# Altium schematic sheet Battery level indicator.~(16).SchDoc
size A3; SheetNumber: 3; SheetTotal: 7
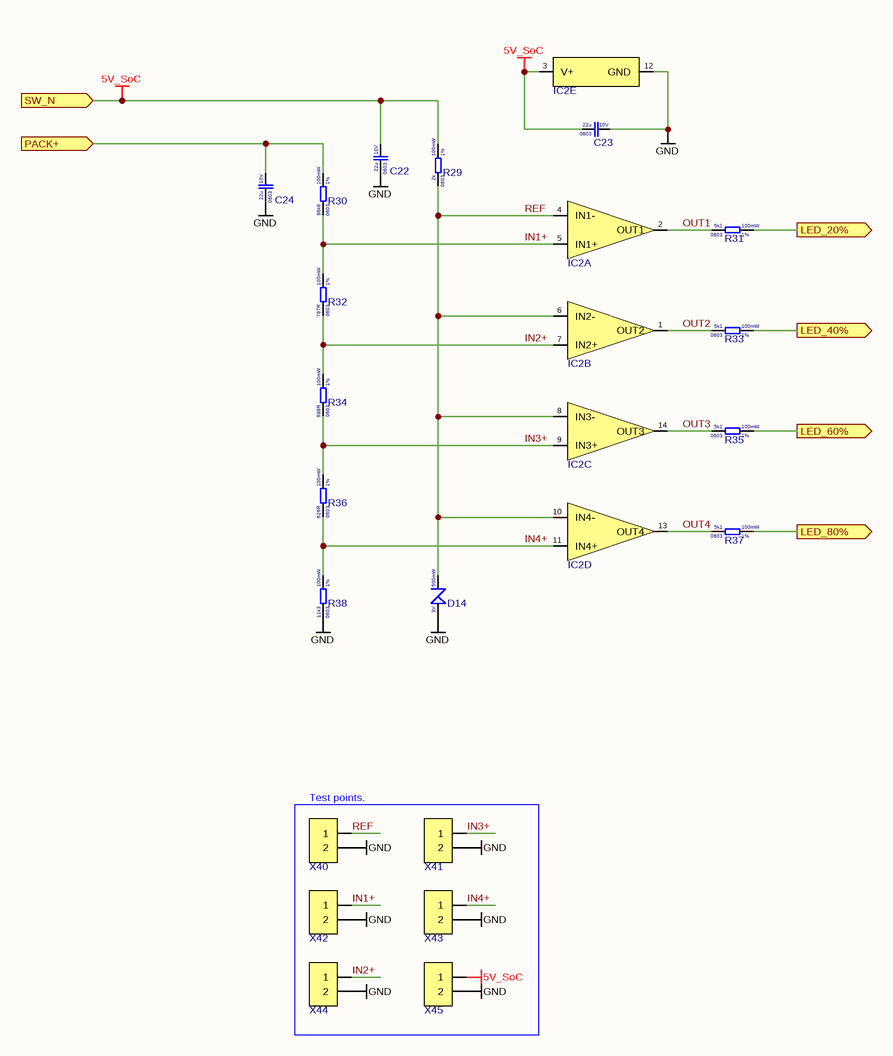
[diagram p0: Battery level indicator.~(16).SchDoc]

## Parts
C22  Voltage Rating: 10V  Case Code (Imperial): 0603  Capacitance: 22u  [CAP 0603]  (hidden comment: CGA0603X5R226M100JT)
C23  Voltage Rating: 10V  Case Code (Imperial): 0603  Capacitance: 22u  [CAP 0603]  (hidden comment: CGA0603X5R226M100JT)
C24  Voltage Rating: 10V  Case Code (Imperial): 0603  Capacitance: 22u  [CAP 0603]  (hidden comment: CGA0603X5R226M100JT)
D14  Power Rating: 500mW  Reverse Voltage: 3V  [SOD-123]  (hidden comment: BZT52C3V0)
IC2  LM339LVPWR  [TSSOP-14]  (value not drawn)  (parts A,B,C,D,E of 5)
R29  Resistance Tolerance: 1%  Resistance: 2k  Power Rating: 100mW  Case Code (Imperial): 0603  [RES_0603]  (hidden comment: 0603WAF2001T5E)
R30  Resistance Tolerance: 1%  Resistance: 86k6  Power Rating: 100mW  Case Code (Imperial): 0603  [RES_0603]  (hidden comment: 0603WAF8662T5E)
R31  Resistance Tolerance: 1%  Resistance: 5k1  Power Rating: 100mW  Case Code (Imperial): 0603  [RES_0603]  (hidden comment: 0603WAF5101T5E)
R32  Resistance Tolerance: 1%  Resistance: 787R  Power Rating: 100mW  Case Code (Imperial): 0603  [RES_0603]  (hidden comment: FRC0603F7870TS)
R33  Resistance Tolerance: 1%  Resistance: 5k1  Power Rating: 100mW  Case Code (Imperial): 0603  [RES_0603]  (hidden comment: 0603WAF5101T5E)
R34  Resistance Tolerance: 1%  Resistance: 698R  Power Rating: 100mW  Case Code (Imperial): 0603  [RES_0603]  (hidden comment: RC0603FR-07698RL)
R35  Resistance Tolerance: 1%  Resistance: 5k1  Power Rating: 100mW  Case Code (Imperial): 0603  [RES_0603]  (hidden comment: 0603WAF5101T5E)
R36  Resistance Tolerance: 1%  Resistance: 626R  Power Rating: 100mW  Case Code (Imperial): 0603  [RES_0603]  (hidden comment: RT0603BRD07626RL)
R37  Resistance Tolerance: 1%  Resistance: 5k1  Power Rating: 100mW  Case Code (Imperial): 0603  [RES_0603]  (hidden comment: 0603WAF5101T5E)
R38  Resistance Tolerance: 1%  Resistance: 11k3  Power Rating: 100mW  Case Code (Imperial): 0603  [RES_0603]  (hidden comment: FRC0603F1132TS)
X40  ZX-PZ1.27-1-2PZZ  [Pin header 1x2 1.27mmP THT Vertical]  (value not drawn)
X41  ZX-PZ1.27-1-2PZZ  [Pin header 1x2 1.27mmP THT Vertical]  (value not drawn)
X42  ZX-PZ1.27-1-2PZZ  [Pin header 1x2 1.27mmP THT Vertical]  (value not drawn)
X43  ZX-PZ1.27-1-2PZZ  [Pin header 1x2 1.27mmP THT Vertical]  (value not drawn)
X44  ZX-PZ1.27-1-2PZZ  [Pin header 1x2 1.27mmP THT Vertical]  (value not drawn)
X45  ZX-PZ1.27-1-2PZZ  [Pin header 1x2 1.27mmP THT Vertical]  (value not drawn)

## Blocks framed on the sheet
Test points.: X40-X45

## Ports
LED_20% (out, see Arhitecture[8C]), LED_40% (out, see Arhitecture[8C]), LED_60% (out, see Arhitecture[8C]), LED_80% (out, see Arhitecture[8D]), PACK+ (in, see Arhitecture[7C], Charger[8A], Power distribution[3B]), SW_N (in, see Arhitecture[7D])

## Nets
5V_SoC: C22.2 C23.1 IC2.3(V+) R29.2 X45.1 ; port SW_N
GND: C22.1 C23.2 C24.1 D14.A IC2.12(GND) R38.1 X40.2 X41.2 X42.2 X43.2 X44.2 X45.2
IN1+: IC2.5(IN1+) R30.1 R32.2 X42.1
IN2+: IC2.7(IN2+) R32.1 R34.2 X44.1
IN3+: IC2.9(IN3+) R34.1 R36.2 X41.1
IN4+: IC2.11(IN4+) R36.1 R38.2 X43.1
LED_20%: R31.2 ; port LED_20%
LED_40%: R33.2 ; port LED_40%
LED_60%: R35.2 ; port LED_60%
LED_80%: R37.2 ; port LED_80%
OUT1: IC2.2(OUT1) R31.1
OUT2: IC2.1(OUT2) R33.1
OUT3: IC2.14(OUT3) R35.1
OUT4: IC2.13(OUT4) R37.1
PACK+: C24.2 R30.2 ; port PACK+
REF: D14.K IC2.4(IN1-) IC2.6(IN2-) IC2.8(IN3-) IC2.10(IN4-) R29.1 X40.1

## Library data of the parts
C22-C24 = CGA0603X5R226M100JT: Cap 22uF 10V 0603 X5R; Manufacturer: HRE
D14 = BZT52C3V0: Zener 3.0V 500mW SOD-123; Manufacturer: Shandong Jingdao Microelectronics
IC2 = LM339LVPWR: Comparator Quad 1.65~5.5V TSSOP-14; Manufacturer: Texas Instruments
R29 = 0603WAF2001T5E: Res 2k 0603 1% 100mW 75V; Manufacturer: Uni-Royal
R30 = 0603WAF8662T5E: Res 86k6 0603 1% 100mW 75V; Manufacturer: Uni-Royal
R31 R33 R35 R37 = 0603WAF5101T5E: Res 5k1 0603 1% 100mW 75V; Manufacturer: Uni-Royal
R32 = FRC0603F7870TS: Res 787R 0603 1% 100mW 75V; Manufacturer: FOJAN
R34 = RC0603FR-07698RL: Res 698R 0603 1% 100mW 75V; Manufacturer: YAGEO
R36 = RT0603BRD07626RL: Res 626R 0603 1% 100mW 75V; Manufacturer: YAGEO
R38 = FRC0603F1132TS: Res 11k3 0603 1% 100mW 75V; Manufacturer: Fojan
X40-X45 = ZX-PZ1.27-1-2PZZ: Pin header 1x2 1.27mmP THT Vertical; Manufacturer: Megastar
